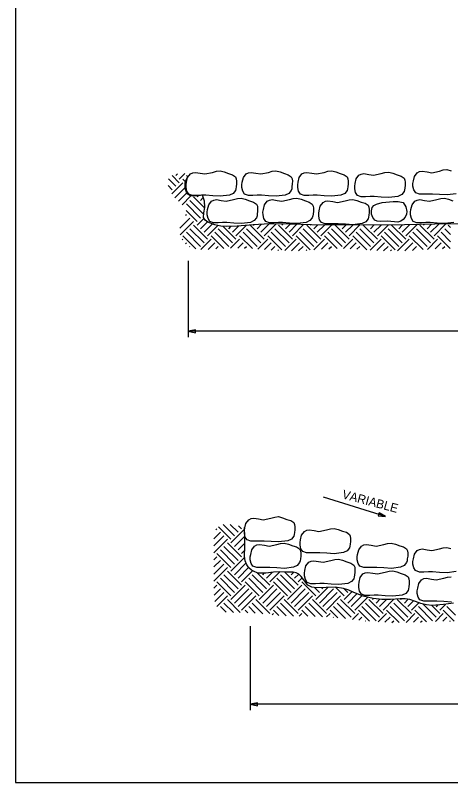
# Model space of a CAD drawing. Extents: x -439.1 to -407.9, y -458.1 to -436.2.
# Drawn here: x -439.11 to -431.65, y -458.05 to -444.91 of the extents above; entities that cross this region are included whole.
import ezdxf

# ---------------------------------------------------------------- set-up
doc = ezdxf.new("R2010")
doc.units = 0
doc.layers.add('Draft_Named_Boundary', color=7, linetype='Continuous')
doc.layers.add('Level 4', color=7, linetype='Continuous')

msp = doc.modelspace()

# ---------------------------------------------------------------- linework, layer by layer
at = {"layer": 'Draft_Named_Boundary'}
msp.add_lwpolyline([(-439.109, -458.051), (-407.859, -458.051), (-407.859, -437.676), (-439.109, -437.676)], close=True, dxfattribs=at)
at = {"layer": 'Level 4'}
for p, q in [((-436.361, -447.835), (-436.484, -447.712)), ((-436.3, -447.775), (-436.425, -447.65)), ((-436.361, -447.653), (-436.332, -447.625)), ((-436.3, -447.714), (-436.206, -447.62)), ((-436.193, -447.761), (-436.24, -447.714)), ((-436.156, -447.676), (-436.179, -447.653)), ((-436.422, -447.896), (-436.491, -447.826)), ((-436.429, -447.964), (-436.24, -447.775)), ((-436.377, -448.033), (-436.199, -447.855)), ((-436.316, -448.094), (-436.171, -447.948)), ((-435.997, -448.017), (-435.978, -447.998)), ((-436.254, -448.153), (-436.102, -448)), ((-435.883, -448.313), (-436.119, -448.078)), ((-435.863, -448.212), (-436.058, -448.017)), ((-435.937, -448.078), (-435.889, -448.03)), ((-435.876, -448.138), (-435.863, -448.126)), ((-435.997, -448.441), (-436.185, -448.254)), ((-435.937, -448.381), (-436.179, -448.138)), ((-436.29, -448.552), (-436.119, -448.381)), ((-436.193, -448.334), (-436.179, -448.32)), ((-435.997, -448.502), (-435.877, -448.382)), ((-436.284, -448.668), (-436.058, -448.441)), ((-435.815, -448.744), (-436.058, -448.502)), ((-435.937, -448.563), (-435.819, -448.445)), ((-435.876, -448.623), (-435.737, -448.484)), ((-435.815, -448.684), (-435.641, -448.509)), ((-435.391, -448.623), (-435.287, -448.519)), ((-435.331, -448.684), (-435.153, -448.507)), ((-434.846, -448.744), (-435.088, -448.502)), ((-435.027, -448.502), (-435.02, -448.495)), ((-434.967, -448.563), (-434.891, -448.487)), ((-434.906, -448.623), (-434.762, -448.479)), ((-434.846, -448.684), (-434.642, -448.48)), ((-434.361, -448.744), (-434.603, -448.502)), ((-434.543, -448.502), (-434.522, -448.482)), ((-434.482, -448.563), (-434.403, -448.483)), ((-434.421, -448.623), (-434.286, -448.488)), ((-434.361, -448.684), (-434.17, -448.493)), ((-433.876, -448.744), (-434.118, -448.502)), ((-434.058, -448.502), (-434.054, -448.499)), ((-433.997, -448.563), (-433.935, -448.5)), ((-433.936, -448.623), (-433.815, -448.501)), ((-433.876, -448.684), (-433.694, -448.502)), ((-433.391, -448.744), (-433.633, -448.502)), ((-433.573, -448.502), (-433.573, -448.502)), ((-433.512, -448.563), (-433.45, -448.501)), ((-433.452, -448.623), (-433.328, -448.5)), ((-433.391, -448.684), (-433.206, -448.499)), ((-432.906, -448.744), (-433.148, -448.502)), ((-433.088, -448.502), (-433.085, -448.5)), ((-433.027, -448.563), (-432.965, -448.5)), ((-432.967, -448.623), (-432.844, -448.501)), ((-432.906, -448.684), (-432.723, -448.501)), ((-432.421, -448.744), (-432.664, -448.502)), ((-432.603, -448.502), (-432.602, -448.501)), ((-432.542, -448.563), (-432.48, -448.5)), ((-432.482, -448.623), (-432.356, -448.498)), ((-432.421, -448.684), (-432.232, -448.495)), ((-431.936, -448.744), (-432.179, -448.502)), ((-432.118, -448.502), (-432.107, -448.491)), ((-432.057, -448.563), (-431.982, -448.487)), ((-431.997, -448.623), (-431.857, -448.483)), ((-431.936, -448.684), (-431.732, -448.48)), ((-431.652, -448.544), (-431.694, -448.502)), ((-435.937, -448.866), (-436.179, -448.623)), ((-435.876, -448.805), (-436.119, -448.563)), ((-435.452, -448.866), (-435.694, -448.623)), ((-435.391, -448.805), (-435.634, -448.563)), ((-435.331, -448.744), (-435.55, -448.525)), ((-435.452, -448.563), (-435.417, -448.527)), ((-434.967, -448.866), (-435.209, -448.623)), ((-434.906, -448.805), (-435.149, -448.563)), ((-434.482, -448.866), (-434.724, -448.623)), ((-434.421, -448.805), (-434.664, -448.563)), ((-433.997, -448.866), (-434.24, -448.623)), ((-433.936, -448.805), (-434.179, -448.563)), ((-433.512, -448.866), (-433.755, -448.623)), ((-433.452, -448.805), (-433.694, -448.563)), ((-433.027, -448.866), (-433.27, -448.623)), ((-432.967, -448.805), (-433.209, -448.563)), ((-432.542, -448.866), (-432.785, -448.623)), ((-432.482, -448.805), (-432.724, -448.563)), ((-432.057, -448.866), (-432.3, -448.623)), ((-431.997, -448.805), (-432.239, -448.563)), ((-431.652, -448.786), (-431.815, -448.623)), ((-431.652, -448.665), (-431.754, -448.563)), ((-436.249, -448.754), (-436.24, -448.744)), ((-436.015, -448.908), (-436.24, -448.684)), ((-435.929, -448.919), (-435.755, -448.744)), ((-435.538, -448.901), (-435.755, -448.684)), ((-435.422, -448.897), (-435.27, -448.744)), ((-435.049, -448.905), (-435.27, -448.684)), ((-434.953, -448.912), (-434.785, -448.744)), ((-434.543, -448.926), (-434.785, -448.684)), ((-434.495, -448.939), (-434.3, -448.744)), ((-434.058, -448.926), (-434.3, -448.684)), ((-433.998, -448.927), (-433.815, -448.744)), ((-433.596, -448.903), (-433.815, -448.684)), ((-433.489, -448.903), (-433.33, -448.744)), ((-433.089, -448.925), (-433.33, -448.684)), ((-433.03, -448.929), (-432.845, -448.744)), ((-432.603, -448.926), (-432.845, -448.684)), ((-432.561, -448.945), (-432.36, -448.744)), ((-432.123, -448.922), (-432.36, -448.684)), ((-432.048, -448.917), (-431.876, -448.744)), ((-431.658, -448.901), (-431.876, -448.684)), ((-436.196, -448.822), (-436.179, -448.805)), ((-436.126, -448.873), (-436.119, -448.866)), ((-435.807, -448.918), (-435.694, -448.805)), ((-435.677, -448.909), (-435.634, -448.866)), ((-435.299, -448.895), (-435.209, -448.805)), ((-435.182, -448.899), (-435.149, -448.866)), ((-434.84, -448.921), (-434.724, -448.805)), ((-434.728, -448.929), (-434.664, -448.866)), ((-434.378, -448.943), (-434.24, -448.805)), ((-434.257, -448.944), (-434.179, -448.866)), ((-433.866, -448.916), (-433.755, -448.805)), ((-433.736, -448.907), (-433.694, -448.866)), ((-433.372, -448.907), (-433.27, -448.805)), ((-433.257, -448.913), (-433.209, -448.866)), ((-432.916, -448.936), (-432.785, -448.805)), ((-432.801, -448.942), (-432.724, -448.866)), ((-432.435, -448.94), (-432.3, -448.805)), ((-432.307, -448.934), (-432.239, -448.866)), ((-431.919, -448.909), (-431.815, -448.805)), ((-431.793, -448.904), (-431.754, -448.866)), ((-434.612, -448.935), (-434.603, -448.926)), ((-434.129, -448.937), (-434.118, -448.926)), ((-432.683, -448.945), (-432.664, -448.926)), ((-436.149, -449.113), (-436.149, -450.423)), ((-421.43, -450.321), (-436.149, -450.321)), ((-432.766, -453.492), (-433.832, -453.161)), ((-435.355, -453.822), (-435.546, -453.631)), ((-435.294, -453.762), (-435.428, -453.628)), ((-435.711, -453.875), (-435.597, -453.762)), ((-435.677, -453.72), (-435.658, -453.701)), ((-435.416, -453.883), (-435.631, -453.667)), ((-435.416, -453.943), (-435.181, -453.709)), ((-435.234, -453.701), (-435.285, -453.65)), ((-435.709, -453.994), (-435.537, -453.822)), ((-435.708, -454.114), (-435.476, -453.883)), ((-435.355, -454.004), (-435.18, -453.829)), ((-435.294, -454.246), (-435.537, -454.004)), ((-435.234, -454.186), (-435.476, -453.943)), ((-435.294, -454.065), (-435.178, -453.948)), ((-435.416, -454.368), (-435.658, -454.125)), ((-435.355, -454.307), (-435.597, -454.065)), ((-435.234, -454.125), (-435.179, -454.07)), ((-435.708, -454.236), (-435.658, -454.186)), ((-435.708, -454.357), (-435.597, -454.246)), ((-435.416, -454.428), (-435.176, -454.189)), ((-435.355, -454.489), (-435.152, -454.286)), ((-435.708, -454.478), (-435.537, -454.307)), ((-435.708, -454.599), (-435.476, -454.368)), ((-435.234, -454.671), (-435.476, -454.428)), ((-435.294, -454.55), (-435.107, -454.362)), ((-435.234, -454.61), (-435.043, -454.419)), ((-435.355, -454.792), (-435.597, -454.55)), ((-435.294, -454.731), (-435.537, -454.489)), ((-434.87, -454.792), (-435.112, -454.55)), ((-434.809, -454.731), (-435.052, -454.489)), ((-434.749, -454.671), (-434.964, -454.456)), ((-434.87, -454.489), (-434.844, -454.463)), ((-434.809, -454.55), (-434.706, -454.446)), ((-434.749, -454.61), (-434.583, -454.444)), ((-434.385, -454.792), (-434.628, -454.55)), ((-434.325, -454.731), (-434.567, -454.489)), ((-434.264, -454.671), (-434.491, -454.444)), ((-434.385, -454.489), (-434.346, -454.45)), ((-434.325, -454.55), (-434.254, -454.479)), ((-434.264, -454.61), (-434.195, -454.541)), ((-435.708, -454.721), (-435.658, -454.671)), ((-435.416, -454.853), (-435.658, -454.61)), ((-435.416, -454.913), (-435.173, -454.671)), ((-434.931, -454.853), (-435.173, -454.61)), ((-434.931, -454.913), (-434.688, -454.671)), ((-434.446, -454.853), (-434.688, -454.61)), ((-434.446, -454.913), (-434.203, -454.671)), ((-433.961, -454.853), (-434.203, -454.61)), ((-435.705, -454.839), (-435.597, -454.731)), ((-435.692, -454.947), (-435.537, -454.792)), ((-435.355, -454.974), (-435.112, -454.731)), ((-435.294, -455.034), (-435.052, -454.792)), ((-434.87, -454.974), (-434.628, -454.731)), ((-434.809, -455.034), (-434.567, -454.792)), ((-434.385, -454.974), (-434.143, -454.731)), ((-434.325, -455.034), (-434.082, -454.792)), ((-433.9, -454.792), (-433.988, -454.704)), ((-433.961, -454.913), (-433.752, -454.705)), ((-433.9, -454.974), (-433.658, -454.731)), ((-433.84, -454.731), (-433.861, -454.71)), ((-433.84, -455.034), (-433.597, -454.792)), ((-433.476, -454.853), (-433.627, -454.701)), ((-433.415, -454.792), (-433.483, -454.724)), ((-433.476, -454.913), (-433.343, -454.78)), ((-433.415, -454.974), (-433.256, -454.814)), ((-435.66, -455.036), (-435.476, -454.853)), ((-435.255, -455.134), (-435.476, -454.913)), ((-435.234, -455.095), (-434.991, -454.853)), ((-434.749, -455.156), (-434.991, -454.913)), ((-434.749, -455.095), (-434.506, -454.853)), ((-434.264, -455.156), (-434.506, -454.913)), ((-434.264, -455.095), (-434.021, -454.853)), ((-433.779, -455.156), (-434.021, -454.913)), ((-433.779, -455.095), (-433.537, -454.853)), ((-433.294, -455.156), (-433.537, -454.913)), ((-433.355, -455.034), (-433.168, -454.847)), ((-433.294, -455.095), (-433.073, -454.874)), ((-432.809, -455.156), (-433.052, -454.913)), ((-432.991, -454.913), (-432.976, -454.898)), ((-432.93, -454.974), (-432.861, -454.905)), ((-432.87, -455.034), (-432.747, -454.911)), ((-432.809, -455.095), (-432.625, -454.911)), ((-432.324, -455.156), (-432.567, -454.913)), ((-432.506, -454.913), (-432.497, -454.904)), ((-432.445, -454.974), (-432.384, -454.913)), ((-432.385, -455.034), (-432.286, -454.936)), ((-435.5, -455.132), (-435.597, -455.034)), ((-435.373, -455.138), (-435.537, -454.974)), ((-435, -455.147), (-435.112, -455.034)), ((-434.868, -455.158), (-435.052, -454.974)), ((-434.468, -455.194), (-434.628, -455.034)), ((-434.343, -455.198), (-434.567, -454.974)), ((-433.973, -455.204), (-434.143, -455.034)), ((-433.847, -455.209), (-434.082, -454.974)), ((-433.451, -455.241), (-433.658, -455.034)), ((-433.355, -455.216), (-433.597, -454.974)), ((-432.93, -455.277), (-433.173, -455.034)), ((-432.87, -455.216), (-433.112, -454.974)), ((-432.445, -455.277), (-432.688, -455.034)), ((-432.385, -455.216), (-432.627, -454.974)), ((-432.324, -455.095), (-432.199, -454.97)), ((-431.961, -455.277), (-432.203, -455.034)), ((-431.9, -455.216), (-432.126, -454.99)), ((-431.839, -455.156), (-431.982, -455.013)), ((-431.9, -455.034), (-431.874, -455.009)), ((-431.839, -455.095), (-431.741, -454.997)), ((-431.569, -455.184), (-431.718, -455.034)), ((-435.127, -455.141), (-435.173, -455.095)), ((-434.708, -455.175), (-434.688, -455.156)), ((-434.597, -455.186), (-434.688, -455.095)), ((-434.247, -455.2), (-434.203, -455.156)), ((-434.096, -455.202), (-434.203, -455.095)), ((-433.776, -455.213), (-433.718, -455.156)), ((-433.586, -455.228), (-433.718, -455.095)), ((-433.662, -455.221), (-433.658, -455.216)), ((-433.332, -455.254), (-433.233, -455.156)), ((-433.043, -455.285), (-433.233, -455.095)), ((-433.223, -455.266), (-433.173, -455.216)), ((-432.892, -455.299), (-432.749, -455.156)), ((-432.777, -455.305), (-432.688, -455.216)), ((-432.536, -455.308), (-432.749, -455.095)), ((-432.414, -455.306), (-432.264, -455.156)), ((-432.291, -455.305), (-432.203, -455.216)), ((-432.063, -455.296), (-432.264, -455.095)), ((-431.912, -455.289), (-431.779, -455.156)), ((-431.786, -455.285), (-431.718, -455.216)), ((-431.59, -455.284), (-431.779, -455.095)), ((-433.114, -455.278), (-433.112, -455.277)), ((-432.66, -455.309), (-432.627, -455.277)), ((-432.166, -455.3), (-432.142, -455.277)), ((-431.665, -455.284), (-431.657, -455.277)), ((-435.084, -455.371), (-435.084, -456.812)), ((-421.785, -456.709), (-435.084, -456.709))]:
    msp.add_line(p, q, dxfattribs=at)
for points in [[(-436.176, -447.767), (-436.158, -447.688), (-436.111, -447.625), (-436.07, -447.606), (-436.025, -447.599), (-435.942, -447.611), (-435.861, -447.625), (-435.73, -447.598), (-435.665, -447.579), (-435.601, -447.573), (-435.531, -447.591), (-435.457, -447.619), (-435.39, -447.64), (-435.339, -447.675), (-435.324, -447.708), (-435.319, -447.747), (-435.32, -447.797), (-435.325, -447.846), (-435.33, -447.878), (-435.339, -447.908), (-435.378, -447.958), (-435.442, -447.988), (-435.598, -448.007), (-435.728, -447.999), (-435.848, -447.99), (-435.92, -447.99), (-435.996, -447.993), (-436.073, -447.993), (-436.137, -447.97), (-436.169, -447.921), (-436.183, -447.859), (-436.184, -447.812), (-436.176, -447.767)], [(-435.221, -447.767), (-435.202, -447.688), (-435.155, -447.625), (-435.115, -447.606), (-435.07, -447.599), (-434.987, -447.611), (-434.905, -447.625), (-434.774, -447.598), (-434.709, -447.579), (-434.646, -447.573), (-434.575, -447.591), (-434.501, -447.619), (-434.434, -447.64), (-434.383, -447.675), (-434.368, -447.708), (-434.363, -447.747), (-434.364, -447.797), (-434.37, -447.846), (-434.374, -447.878), (-434.383, -447.908), (-434.423, -447.958), (-434.486, -447.988), (-434.642, -448.007), (-434.772, -447.999), (-434.892, -447.99), (-434.964, -447.99), (-435.04, -447.993), (-435.117, -447.993), (-435.181, -447.97), (-435.214, -447.921), (-435.227, -447.859), (-435.228, -447.812), (-435.221, -447.767)], [(-434.265, -447.767), (-434.247, -447.688), (-434.199, -447.625), (-434.159, -447.606), (-434.114, -447.599), (-434.031, -447.611), (-433.95, -447.625), (-433.818, -447.598), (-433.753, -447.579), (-433.69, -447.573), (-433.62, -447.591), (-433.546, -447.619), (-433.478, -447.64), (-433.427, -447.675), (-433.413, -447.708), (-433.408, -447.747), (-433.409, -447.797), (-433.414, -447.846), (-433.419, -447.878), (-433.427, -447.908), (-433.467, -447.958), (-433.531, -447.988), (-433.687, -448.007), (-433.817, -447.999), (-433.937, -447.99), (-434.008, -447.99), (-434.084, -447.993), (-434.161, -447.993), (-434.226, -447.97), (-434.258, -447.921), (-434.272, -447.859), (-434.272, -447.812), (-434.265, -447.767)], [(-433.288, -447.788), (-433.27, -447.709), (-433.223, -447.647), (-433.182, -447.627), (-433.137, -447.62), (-433.054, -447.633), (-432.973, -447.647), (-432.841, -447.619), (-432.777, -447.6), (-432.713, -447.594), (-432.643, -447.612), (-432.569, -447.64), (-432.502, -447.661), (-432.45, -447.696), (-432.436, -447.73), (-432.431, -447.768), (-432.432, -447.818), (-432.437, -447.867), (-432.442, -447.899), (-432.45, -447.929), (-432.49, -447.979), (-432.554, -448.009), (-432.71, -448.028), (-432.84, -448.021), (-432.96, -448.011), (-433.031, -448.011), (-433.108, -448.015), (-433.185, -448.015), (-433.249, -447.992), (-433.281, -447.943), (-433.295, -447.88), (-433.296, -447.833), (-433.288, -447.788)], [(-435.815, -448.234), (-435.797, -448.155), (-435.75, -448.093), (-435.709, -448.073), (-435.664, -448.066), (-435.581, -448.079), (-435.5, -448.093), (-435.369, -448.065), (-435.304, -448.046), (-435.24, -448.04), (-435.17, -448.058), (-435.096, -448.086), (-435.029, -448.107), (-434.977, -448.142), (-434.963, -448.176), (-434.958, -448.214), (-434.959, -448.264), (-434.964, -448.313), (-434.969, -448.345), (-434.977, -448.375), (-435.017, -448.425), (-435.081, -448.455), (-435.237, -448.474), (-435.367, -448.467), (-435.487, -448.457), (-435.559, -448.457), (-435.635, -448.461), (-435.712, -448.461), (-435.776, -448.438), (-435.808, -448.389), (-435.822, -448.326), (-435.823, -448.279), (-435.815, -448.234)], [(-434.86, -448.234), (-434.841, -448.155), (-434.794, -448.093), (-434.754, -448.073), (-434.709, -448.066), (-434.626, -448.079), (-434.544, -448.093), (-434.413, -448.065), (-434.348, -448.046), (-434.285, -448.04), (-434.214, -448.058), (-434.14, -448.086), (-434.073, -448.107), (-434.022, -448.142), (-434.007, -448.176), (-434.002, -448.214), (-434.003, -448.264), (-434.009, -448.313), (-434.013, -448.345), (-434.022, -448.375), (-434.062, -448.425), (-434.125, -448.455), (-434.281, -448.474), (-434.411, -448.467), (-434.531, -448.457), (-434.603, -448.457), (-434.679, -448.461), (-434.756, -448.461), (-434.82, -448.438), (-434.853, -448.389), (-434.866, -448.326), (-434.867, -448.279), (-434.86, -448.234)], [(-433.904, -448.255), (-433.886, -448.177), (-433.838, -448.114), (-433.798, -448.094), (-433.753, -448.088), (-433.67, -448.1), (-433.589, -448.114), (-433.457, -448.086), (-433.392, -448.067), (-433.329, -448.061), (-433.258, -448.079), (-433.184, -448.107), (-433.117, -448.128), (-433.066, -448.163), (-433.052, -448.197), (-433.046, -448.235), (-433.047, -448.285), (-433.053, -448.334), (-433.058, -448.366), (-433.066, -448.396), (-433.106, -448.446), (-433.17, -448.476), (-433.326, -448.495), (-433.456, -448.488), (-433.576, -448.479), (-433.647, -448.479), (-433.723, -448.482), (-433.8, -448.482), (-433.865, -448.459), (-433.897, -448.41), (-433.911, -448.347), (-433.911, -448.3), (-433.904, -448.255)], [(-432.463, -448.117), (-432.418, -448.186), (-432.4, -448.266), (-432.409, -448.317), (-432.432, -448.366), (-432.465, -448.407), (-432.506, -448.436), (-432.559, -448.45), (-432.616, -448.448), (-432.739, -448.436), (-432.855, -448.44), (-432.908, -448.435), (-432.952, -448.415), (-432.986, -448.372), (-433.006, -448.315), (-433.009, -448.255), (-432.994, -448.202), (-432.965, -448.168), (-432.924, -448.144), (-432.824, -448.117), (-432.639, -448.096), (-432.551, -448.1), (-432.463, -448.117)], [(-436.022, -450.294), (-436.149, -450.321), (-436.022, -450.347)], [(-435.177, -453.689), (-435.159, -453.611), (-435.112, -453.548), (-435.071, -453.528), (-435.026, -453.522), (-434.943, -453.534), (-434.862, -453.548), (-434.731, -453.52), (-434.666, -453.501), (-434.602, -453.495), (-434.532, -453.513), (-434.458, -453.541), (-434.391, -453.562), (-434.34, -453.597), (-434.325, -453.631), (-434.32, -453.669), (-434.321, -453.719), (-434.326, -453.768), (-434.331, -453.8), (-434.34, -453.83), (-434.379, -453.88), (-434.443, -453.91), (-434.599, -453.929), (-434.729, -453.922), (-434.849, -453.913), (-434.921, -453.913), (-434.997, -453.916), (-435.074, -453.916), (-435.138, -453.893), (-435.17, -453.844), (-435.184, -453.781), (-435.185, -453.734), (-435.177, -453.689)], [(-432.895, -453.48), (-432.766, -453.492), (-432.879, -453.43)], [(-432.895, -453.48), (-432.766, -453.492), (-432.879, -453.43)], [(-434.224, -453.89), (-434.205, -453.811), (-434.158, -453.749), (-434.118, -453.729), (-434.073, -453.722), (-433.99, -453.735), (-433.908, -453.749), (-433.777, -453.721), (-433.712, -453.702), (-433.649, -453.696), (-433.578, -453.714), (-433.504, -453.742), (-433.437, -453.763), (-433.386, -453.798), (-433.371, -453.832), (-433.366, -453.87), (-433.367, -453.92), (-433.373, -453.969), (-433.377, -454.001), (-433.386, -454.031), (-433.426, -454.081), (-433.489, -454.111), (-433.645, -454.13), (-433.775, -454.123), (-433.895, -454.113), (-433.967, -454.113), (-434.043, -454.117), (-434.12, -454.117), (-434.184, -454.094), (-434.217, -454.045), (-434.23, -453.982), (-434.231, -453.935), (-434.224, -453.89)], [(-435.077, -454.141), (-435.059, -454.062), (-435.011, -454), (-434.971, -453.98), (-434.926, -453.973), (-434.843, -453.986), (-434.762, -454), (-434.63, -453.972), (-434.565, -453.953), (-434.502, -453.947), (-434.431, -453.965), (-434.357, -453.993), (-434.29, -454.014), (-434.239, -454.049), (-434.225, -454.082), (-434.219, -454.121), (-434.22, -454.171), (-434.226, -454.22), (-434.231, -454.252), (-434.239, -454.282), (-434.279, -454.332), (-434.343, -454.362), (-434.499, -454.381), (-434.629, -454.374), (-434.748, -454.364), (-434.82, -454.364), (-434.896, -454.368), (-434.973, -454.368), (-435.038, -454.345), (-435.07, -454.296), (-435.084, -454.233), (-435.084, -454.186), (-435.077, -454.141)], [(-433.245, -454.141), (-433.227, -454.062), (-433.179, -454), (-433.139, -453.98), (-433.094, -453.973), (-433.011, -453.986), (-432.93, -454), (-432.798, -453.972), (-432.733, -453.953), (-432.67, -453.947), (-432.599, -453.965), (-432.525, -453.993), (-432.458, -454.014), (-432.407, -454.049), (-432.393, -454.082), (-432.387, -454.121), (-432.388, -454.171), (-432.394, -454.22), (-432.399, -454.252), (-432.407, -454.282), (-432.447, -454.332), (-432.511, -454.362), (-432.667, -454.381), (-432.797, -454.374), (-432.916, -454.364), (-432.988, -454.364), (-433.064, -454.368), (-433.141, -454.368), (-433.206, -454.345), (-433.238, -454.296), (-433.252, -454.233), (-433.252, -454.186), (-433.245, -454.141)], [(-434.148, -454.417), (-434.13, -454.338), (-434.083, -454.276), (-434.042, -454.256), (-433.997, -454.249), (-433.915, -454.262), (-433.833, -454.276), (-433.702, -454.248), (-433.637, -454.229), (-433.573, -454.223), (-433.503, -454.241), (-433.429, -454.269), (-433.362, -454.29), (-433.311, -454.325), (-433.296, -454.359), (-433.291, -454.397), (-433.292, -454.447), (-433.297, -454.496), (-433.302, -454.528), (-433.311, -454.558), (-433.351, -454.608), (-433.414, -454.638), (-433.57, -454.657), (-433.7, -454.65), (-433.82, -454.64), (-433.892, -454.64), (-433.968, -454.644), (-434.045, -454.644), (-434.109, -454.621), (-434.141, -454.572), (-434.155, -454.509), (-434.156, -454.462), (-434.148, -454.417)], [(-433.22, -454.618), (-433.202, -454.539), (-433.154, -454.476), (-433.114, -454.457), (-433.069, -454.45), (-432.986, -454.462), (-432.904, -454.476), (-432.773, -454.448), (-432.708, -454.43), (-432.645, -454.424), (-432.574, -454.442), (-432.5, -454.47), (-432.433, -454.491), (-432.382, -454.526), (-432.368, -454.559), (-432.362, -454.598), (-432.363, -454.648), (-432.369, -454.697), (-432.374, -454.729), (-432.382, -454.759), (-432.422, -454.809), (-432.485, -454.839), (-432.642, -454.858), (-432.772, -454.85), (-432.891, -454.841), (-432.963, -454.841), (-433.039, -454.844), (-433.116, -454.844), (-433.18, -454.821), (-433.213, -454.772), (-433.226, -454.71), (-433.227, -454.663), (-433.22, -454.618)], [(-434.958, -456.683), (-435.084, -456.709), (-434.958, -456.735)]]:
    msp.add_lwpolyline(points, close=True, dxfattribs=at)
for points in [[(-431.556, -447.967), (-431.712, -447.985), (-431.842, -447.978), (-431.962, -447.969), (-432.033, -447.969), (-432.109, -447.972), (-432.187, -447.972), (-432.251, -447.949), (-432.283, -447.9), (-432.297, -447.837), (-432.297, -447.791), (-432.29, -447.745), (-432.29, -447.745), (-432.272, -447.667), (-432.224, -447.604), (-432.184, -447.585), (-432.139, -447.578), (-432.056, -447.59), (-431.975, -447.604), (-431.843, -447.576), (-431.778, -447.557), (-431.715, -447.552), (-431.645, -447.57)], [(-435.904, -447.99), (-435.964, -447.998), (-436.027, -448.003), (-436.075, -448.005), (-436.12, -447.997), (-436.153, -447.973), (-436.178, -447.939), (-436.198, -447.877), (-436.201, -447.811), (-436.197, -447.776), (-436.189, -447.742), (-436.16, -447.681), (-436.116, -447.629)], [(-431.402, -448.478), (-431.922, -448.485), (-432.442, -448.499), (-432.877, -448.501), (-433.313, -448.499), (-433.674, -448.503), (-434.035, -448.499), (-434.395, -448.483), (-434.757, -448.478), (-435.036, -448.496), (-435.309, -448.521), (-435.495, -448.528), (-435.59, -448.52), (-435.691, -448.499), (-435.812, -448.451), (-435.857, -448.416), (-435.883, -448.372), (-435.879, -448.291), (-435.861, -448.202), (-435.87, -448.093), (-435.904, -447.99)], [(-431.598, -448.455), (-431.754, -448.474), (-431.884, -448.467), (-432.004, -448.457), (-432.076, -448.457), (-432.152, -448.461), (-432.229, -448.461), (-432.293, -448.438), (-432.325, -448.389), (-432.339, -448.326), (-432.34, -448.279), (-432.333, -448.234), (-432.333, -448.234), (-432.314, -448.155), (-432.267, -448.093), (-432.226, -448.073), (-432.181, -448.066), (-432.099, -448.079), (-432.017, -448.093), (-431.886, -448.065), (-431.821, -448.046), (-431.758, -448.04), (-431.687, -448.058), (-431.613, -448.086)], [(-435.062, -454.411), (-435.108, -454.37), (-435.143, -454.322), (-435.17, -454.25), (-435.181, -454.172), (-435.178, -454.008), (-435.18, -453.842), (-435.181, -453.679)], [(-431.557, -454.437), (-431.713, -454.456), (-431.843, -454.449), (-431.963, -454.44), (-432.034, -454.44), (-432.111, -454.443), (-432.188, -454.443), (-432.252, -454.42), (-432.284, -454.371), (-432.298, -454.308), (-432.299, -454.261), (-432.291, -454.216), (-432.291, -454.216), (-432.273, -454.138), (-432.226, -454.075), (-432.185, -454.055), (-432.14, -454.049), (-432.057, -454.061), (-431.976, -454.075), (-431.845, -454.047), (-431.78, -454.028), (-431.716, -454.022), (-431.646, -454.04)], [(-431.601, -454.975), (-431.777, -455.002), (-431.971, -455.015), (-432.067, -455.007), (-432.16, -454.985), (-432.256, -454.948), (-432.352, -454.915), (-432.433, -454.903), (-432.515, -454.903), (-432.684, -454.915), (-432.833, -454.915), (-432.98, -454.898), (-433.148, -454.855), (-433.312, -454.793), (-433.398, -454.755), (-433.486, -454.723), (-433.629, -454.701), (-433.782, -454.706), (-433.953, -454.715), (-434.031, -454.704), (-434.096, -454.671), (-434.173, -454.573), (-434.21, -454.52), (-434.253, -454.479), (-434.299, -454.458), (-434.351, -454.448), (-434.463, -454.444), (-434.578, -454.441), (-434.689, -454.444), (-434.82, -454.463), (-434.951, -454.461), (-435.009, -454.442), (-435.062, -454.411)], [(-431.638, -454.958), (-431.768, -454.951), (-431.887, -454.942), (-431.959, -454.942), (-432.035, -454.945), (-432.112, -454.945), (-432.177, -454.922), (-432.209, -454.873), (-432.223, -454.81), (-432.223, -454.763), (-432.216, -454.718), (-432.216, -454.718), (-432.198, -454.639), (-432.15, -454.577), (-432.11, -454.557), (-432.065, -454.551), (-431.982, -454.563), (-431.901, -454.577), (-431.769, -454.549), (-431.704, -454.53), (-431.641, -454.524)]]:
    msp.add_lwpolyline(points, dxfattribs=at)

# ---------------------------------------------------------------- texts
msp.add_text('VARIABLE', height=0.15, rotation=345, dxfattribs=at).set_placement((-433.522, -453.178))

doc.saveas('drawing.dxf')
